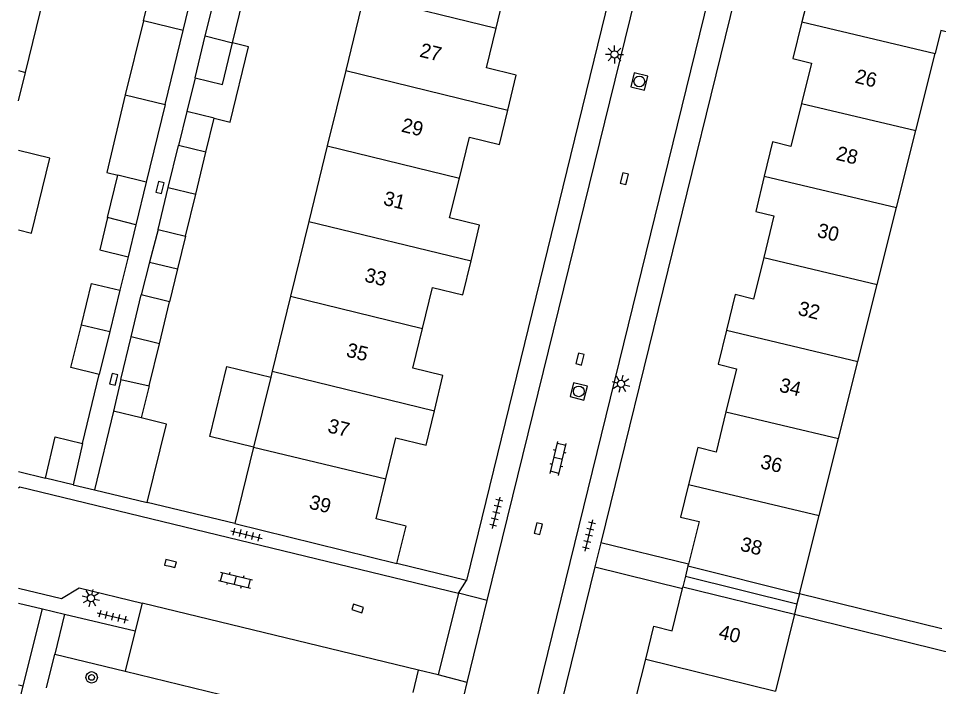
# Model space of a CAD drawing. Extents: x 128000 to 131008, y 398996 to 402500.
# Drawn here: x 128000 to 128064.3, y 399441.3 to 399488 of the extents above; entities that cross this region are included whole.
import ezdxf

# ---------------------------------------------------------------- set-up
doc = ezdxf.new("R2010")
doc.units = 0
for name, color, linetype in [('gg-afsc-erfafscheiding', 7, 'Continuous'), ('gg-afsc-hekwerk', 7, 'Continuous'), ('gg-afsc-muur', 7, 'Continuous'), ('gg-anno-huisnummerreeks BGT', 7, 'Continuous'), ('gg-bbg-bijgebouw', 7, 'Continuous'), ('gg-bbg-gedigitaliseerde bebouwing', 7, 'Continuous'), ('gg-bbg-gedigitaliseerde bijgebouw', 7, 'Continuous'), ('gg-bbg-hoofdgebouw', 7, 'Continuous'), ('gg-bbg-luifel en loopbrug', 7, 'Continuous'), ('gg-bbg-onder overbouw', 7, 'Continuous'), ('gg-bbg-pand overbouw', 7, 'Continuous'), ('gg-bbg-tussenscheiding', 7, 'Continuous'), ('gg-bbg-tussenscheiding niveau 01', 7, 'Continuous'), ('gg-knt-verharding', 7, 'Continuous'), ('gg-knt-verharding nz', 7, 'Continuous'), ('gt-grn-weggrens', 7, 'Continuous'), ('gt-symb-boom', 7, 'Continuous'), ('gt-symb-klinker verharding', 7, 'Continuous'), ('gt-symb-kolk', 7, 'Continuous'), ('gt-symb-lichtmast', 7, 'Continuous'), ('gt-symb-rioolschacht', 7, 'Continuous'), ('gt-symb-tegel verharding', 7, 'Continuous')]:
    doc.layers.add(name, color=color, linetype=linetype)

# ---------------------------------------------------------------- blocks, each defined once
blk = doc.blocks.new('gt0-KOLK')
at = {"layer": 'gt-symb-kolk'}
blk.add_lwpolyline([(0, 0), (0.375, 0), (0.375, 0.4), (-0.375, 0.4), (-0.375, 0), (0, 0)], dxfattribs=at)
blk = doc.blocks.new('gt0-LMAST')
at = {"layer": 'gt-symb-lichtmast'}
for p, q in [((-0.182, 0.173), (-0.447, 0.438)), ((-0.005, 0.246), (-0.005, 0.621)), ((0.172, 0.173), (0.437, 0.438)), ((-0.255, -0.004), (-0.63, -0.004)), ((-0.182, -0.181), (-0.447, -0.446)), ((-0.005, -0.254), (-0.005, -0.629)), ((0.437, -0.446), (0.172, -0.181)), ((0.245, -0.004), (0.62, -0.004))]:
    blk.add_line(p, q, dxfattribs=at)
blk.add_circle((-0.005, -0.004), 0.25, dxfattribs=at)
blk = doc.blocks.new('gt0-RS')
at = {"layer": 'gt-symb-rioolschacht'}
blk.add_lwpolyline([(-0.5, -0.5), (0.5, -0.5), (0.5, 0.5), (-0.5, 0.5)], close=True, dxfattribs=at)
blk.add_circle((0, 0), 0.375, dxfattribs=at)
blk = doc.blocks.new('gt0-TEG1')
at = {"layer": 'gt-symb-tegel verharding'}
for p, q in [((-1.125, 0), (1.125, 0)), ((-0.9, -0.25), (-0.9, 0.25)), ((-0.45, -0.25), (-0.45, 0.25)), ((0, -0.25), (0, 0.25)), ((0.45, -0.25), (0.45, 0.25)), ((0.9, -0.25), (0.9, 0.25))]:
    blk.add_line(p, q, dxfattribs=at)
blk = doc.blocks.new('gt0-KL1')
at = {"layer": 'gt-symb-klinker verharding'}
for p, q in [((-1.15, 0.3), (1.15, 0.3)), ((-1, -0.3), (-1, 0.3)), ((-0.5, 0.3), (-0.5, 0.45)), ((0, -0.3), (0, 0.3)), ((0.5, 0.3), (0.5, 0.45)), ((1, -0.3), (1, 0.3)), ((-1.15, -0.3), (1.15, -0.3)), ((-0.5, -0.45), (-0.5, -0.3)), ((0.5, -0.45), (0.5, -0.3))]:
    blk.add_line(p, q, dxfattribs=at)
blk = doc.blocks.new('gt0-BOOM')
at = {"layer": 'gt-symb-boom'}
for radius in [0.4, 0.2]:
    blk.add_circle((0, 0), radius, dxfattribs=at)

msp = doc.modelspace()

# ---------------------------------------------------------------- linework, layer by layer
at = {"layer": 'gg-afsc-erfafscheiding'}
for p, q in [((128007.665, 399471.364), (128007.09, 399469.019)), ((128004.48, 399458.323), (128005.656, 399463.142)), ((128064.553, 399445.371), (128054.591, 399447.82))]:
    msp.add_line(p, q, dxfattribs=at)
msp.add_lwpolyline([(128054.25, 399446.39), (128067.198, 399443.207), (128066.58, 399440.802)], dxfattribs=at)
at = {"layer": 'gg-afsc-hekwerk'}
for p, q in [((128001.967, 399441.245), (128002.542, 399443.609)), ((128002.542, 399443.609), (128007.47, 399442.41)), ((128007.47, 399442.41), (128026.82, 399437.72))]:
    msp.add_line(p, q, dxfattribs=at)
at = {"layer": 'gg-afsc-muur'}
for p, q in [((128000, 399456.352), (128001.888, 399455.886)), ((128015.13, 399452.72), (128009.009, 399454.186)), ((128046.827, 399449.877), (128040.705, 399451.381)), ((128040.294, 399449.707), (128046.421, 399448.191))]:
    msp.add_line(p, q, dxfattribs=at)
at = {"layer": 'gg-bbg-bijgebouw'}
for p, q in [((128006.652, 399460.575), (128005.317, 399455.085)), ((128008.59, 399460.103), (128006.652, 399460.575)), ((128001.888, 399455.886), (128002.578, 399458.787)), ((128004.48, 399458.323), (128003.831, 399455.424)), ((128003.831, 399455.424), (128001.888, 399455.886)), ((128005.317, 399455.085), (128009.009, 399454.186)), ((128000, 399447.174), (128001.69, 399446.76))]:
    msp.add_line(p, q, dxfattribs=at)
msp.add_lwpolyline([(128009.009, 399454.186), (128010.345, 399459.676), (128008.59, 399460.103)], dxfattribs=at)
at = {"layer": 'gg-bbg-gedigitaliseerde bebouwing'}
msp.add_line((128054.25, 399446.39), (128052.93, 399441.02), dxfattribs=at)
msp.add_lwpolyline([(128072.212, 399489.204), (128071.304, 399485.502), (128064.48, 399487.175), (128064.084, 399485.56)], dxfattribs=at)
at = {"layer": 'gg-bbg-gedigitaliseerde bijgebouw'}
for p, q in [((128011.516, 399487.159), (128012.822, 399492.516)), ((128013.062, 399486.782), (128013.778, 399489.713)), ((128014.968, 399486.313), (128015.683, 399489.25)), ((128008.733, 399487.836), (128007.472, 399482.662)), ((128010.254, 399481.984), (128011.516, 399487.159)), ((128012.346, 399483.85), (128013.062, 399486.782)), ((128010.254, 399481.984), (128008.936, 399476.577)), ((128010.477, 399476.202), (128011.195, 399479.142)), ((128013.11, 399478.676), (128011.195, 399479.142)), ((128012.395, 399475.738), (128013.11, 399478.676)), ((128006.231, 399474.108), (128006.953, 399477.065)), ((128008.936, 399476.577), (128008.21, 399473.59)), ((128009.76, 399473.269), (128010.477, 399476.202)), ((128011.68, 399472.802), (128012.395, 399475.738)), ((128008.21, 399473.59), (128006.231, 399474.108)), ((128009.76, 399473.269), (128011.68, 399472.802)), ((128007.09, 399469.019), (128006.385, 399466.13)), ((128007.877, 399465.767), (128008.584, 399468.702)), ((128010.565, 399468.22), (128008.584, 399468.702)), ((128009.851, 399465.286), (128010.565, 399468.22)), ((128006.385, 399466.13), (128005.656, 399463.142)), ((128007.16, 399462.79), (128007.877, 399465.767)), ((128009.138, 399462.355), (128009.851, 399465.286)), ((128007.16, 399462.79), (128009.138, 399462.355)), ((128002.578, 399458.787), (128004.48, 399458.323)), ((128000.341, 399441.385), (128001.69, 399446.76)), ((128000, 399440.024), (128000.341, 399441.385))]:
    msp.add_line(p, q, dxfattribs=at)
for points in [[(128008.733, 399487.836), (128010.04, 399493.194), (128012.822, 399492.516)], [(128012.346, 399483.85), (128014.256, 399483.385), (128014.968, 399486.313)], [(128007.472, 399482.662), (128006.172, 399477.253), (128006.953, 399477.065)], [(128004.402, 399466.611), (128005.108, 399469.503), (128007.09, 399469.019)], [(128005.656, 399463.142), (128003.674, 399463.625), (128004.402, 399466.611)]]:
    msp.add_lwpolyline(points, dxfattribs=at)
at = {"layer": 'gg-bbg-hoofdgebouw'}
for p, q in [((128055.71, 399491.59), (128054.769, 399487.766)), ((128000.487, 399484.241), (128001.781, 399489.524)), ((128024.156, 399489.589), (128022.878, 399484.37)), ((128062.732, 399480.183), (128064.084, 399485.56)), ((128000, 399482.251), (128000.487, 399484.241)), ((128022.878, 399484.37), (128021.59, 399479.105)), ((128061.379, 399474.806), (128062.732, 399480.183)), ((128021.59, 399479.105), (128020.297, 399473.827)), ((128060.026, 399469.428), (128061.379, 399474.806)), ((128020.297, 399473.827), (128019.017, 399468.596)), ((128058.674, 399464.052), (128060.026, 399469.428)), ((128019.017, 399468.596), (128017.736, 399463.363)), ((128057.321, 399458.675), (128058.674, 399464.052)), ((128017.634, 399462.948), (128016.439, 399458.066)), ((128017.736, 399463.363), (128017.634, 399462.948)), ((128055.969, 399453.298), (128057.321, 399458.675)), ((128016.439, 399458.066), (128015.13, 399452.72)), ((128054.591, 399447.82), (128055.969, 399453.298)), ((128015.13, 399452.72), (128026.45, 399449.94)), ((128046.827, 399449.877), (128046.8, 399449.77)), ((128046.421, 399448.191), (128046.45, 399448.31))]:
    msp.add_line(p, q, dxfattribs=at)
for points in [[(128033.39, 399487.338), (128034.08, 399490.17), (128036.18, 399489.65), (128036.778, 399492.07)], [(128054.769, 399487.766), (128054.14, 399485.21), (128055.431, 399484.89), (128054.739, 399482.075)], [(128034.201, 399481.588), (128034.8, 399484.04), (128032.71, 399484.55), (128033.39, 399487.338)], [(128030.825, 399476.851), (128031.531, 399479.72), (128033.621, 399479.21), (128034.201, 399481.588)], [(128054.739, 399482.075), (128054, 399479.07), (128052.72, 399479.39), (128052.138, 399476.994)], [(128031.639, 399471.085), (128032.24, 399473.56), (128030.14, 399474.07), (128030.825, 399476.851)], [(128052.138, 399476.994), (128051.54, 399474.53), (128052.81, 399474.22), (128052.094, 399471.306)], [(128052.094, 399471.306), (128051.38, 399468.4), (128050.1, 399468.72), (128049.491, 399466.226)], [(128028.251, 399466.355), (128028.95, 399469.21), (128031.06, 399468.7), (128031.639, 399471.085)], [(128029.073, 399460.599), (128029.67, 399463.06), (128027.57, 399463.57), (128028.251, 399466.355)], [(128049.491, 399466.226), (128048.91, 399463.85), (128050.19, 399463.54), (128049.452, 399460.538)], [(128025.683, 399455.853), (128026.38, 399458.71), (128028.49, 399458.2), (128029.073, 399460.599)], [(128049.452, 399460.538), (128048.76, 399457.72), (128047.48, 399458.03), (128046.841, 399455.459)], [(128026.45, 399449.94), (128027.11, 399452.54), (128025.001, 399453.06), (128025.683, 399455.853)], [(128046.841, 399455.459), (128046.27, 399453.16), (128047.58, 399452.87), (128046.827, 399449.877)], [(128043.846, 399443.25), (128044.42, 399445.56), (128045.69, 399445.22), (128046.421, 399448.191)], [(128043.816, 399437.551), (128044.51, 399440.37), (128043.21, 399440.69), (128043.846, 399443.25)]]:
    msp.add_lwpolyline(points, dxfattribs=at)
at = {"layer": 'gg-bbg-luifel en loopbrug'}
for p, q in [((128012.346, 399483.85), (128011.771, 399481.496)), ((128011.771, 399481.496), (128011.195, 399479.142)), ((128013.683, 399481.031), (128011.771, 399481.496)), ((128013.11, 399478.676), (128013.683, 399481.031)), ((128008.21, 399473.59), (128007.665, 399471.364)), ((128009.76, 399473.269), (128009.172, 399470.986)), ((128011.68, 399472.802), (128011.123, 399470.511)), ((128009.172, 399470.986), (128008.584, 399468.702)), ((128009.172, 399470.986), (128011.123, 399470.511)), ((128011.123, 399470.511), (128010.565, 399468.22)), ((128007.16, 399462.79), (128006.652, 399460.575)), ((128009.138, 399462.355), (128008.59, 399460.103))]:
    msp.add_line(p, q, dxfattribs=at)
for points in [[(128013.683, 399481.031), (128014.803, 399480.758), (128016.083, 399486.023), (128014.968, 399486.313)], [(128000, 399473.229), (128000.927, 399473.003), (128002.202, 399478.244), (128000, 399478.78)], [(128006.231, 399474.108), (128005.681, 399471.847), (128007.665, 399471.364)], [(128016.439, 399458.066), (128013.387, 399458.808), (128014.575, 399463.692), (128017.634, 399462.948)]]:
    msp.add_lwpolyline(points, dxfattribs=at)
at = {"layer": 'gg-bbg-onder overbouw'}
for p, q in [((128046.8, 399449.77), (128054.591, 399447.82)), ((128046.45, 399448.31), (128054.25, 399446.39))]:
    msp.add_line(p, q, dxfattribs=at)
at = {"layer": 'gg-bbg-pand overbouw'}
for p, q in [((128046.8, 399449.77), (128046.625, 399449.04)), ((128046.625, 399449.04), (128046.45, 399448.31)), ((128054.591, 399447.82), (128054.421, 399447.105)), ((128054.421, 399447.105), (128054.25, 399446.39))]:
    msp.add_line(p, q, dxfattribs=at)
at = {"layer": 'gg-bbg-tussenscheiding'}
for p, q in [((128024.156, 399489.589), (128033.39, 399487.338)), ((128011.516, 399487.159), (128008.733, 399487.836)), ((128054.769, 399487.766), (128064.084, 399485.56)), ((128013.062, 399486.782), (128014.968, 399486.313)), ((128000, 399484.359), (128000.487, 399484.241)), ((128022.878, 399484.37), (128034.201, 399481.588)), ((128007.472, 399482.662), (128010.254, 399481.984)), ((128054.739, 399482.075), (128062.732, 399480.183)), ((128021.59, 399479.105), (128030.825, 399476.851)), ((128008.936, 399476.577), (128006.953, 399477.065)), ((128052.138, 399476.994), (128061.379, 399474.806)), ((128010.477, 399476.202), (128012.395, 399475.738)), ((128020.297, 399473.827), (128031.639, 399471.085)), ((128052.094, 399471.306), (128060.026, 399469.428)), ((128019.017, 399468.596), (128028.251, 399466.355)), ((128004.402, 399466.611), (128006.385, 399466.13)), ((128049.491, 399466.226), (128058.674, 399464.052)), ((128009.851, 399465.286), (128007.877, 399465.767)), ((128017.736, 399463.363), (128029.073, 399460.599)), ((128049.452, 399460.538), (128057.321, 399458.675)), ((128016.439, 399458.066), (128025.683, 399455.853)), ((128046.841, 399455.459), (128055.969, 399453.298)), ((128043.846, 399443.25), (128052.93, 399441.02)), ((128000, 399441.467), (128000.341, 399441.385))]:
    msp.add_line(p, q, dxfattribs=at)
at = {"layer": 'gg-bbg-tussenscheiding niveau 01'}
msp.add_line((128046.625, 399449.04), (128054.421, 399447.105), dxfattribs=at)
at = {"layer": 'gg-knt-verharding'}
for p, q in [((128042.989, 399496.39), (128031.33, 399448.74)), ((128051.27, 399494.35), (128040.705, 399451.381)), ((128032.775, 399447.345), (128044.065, 399493.284)), ((128048.865, 399492.067), (128035.151, 399436.183)), ((128031.33, 399448.74), (128026.45, 399449.94)), ((128030.77, 399447.85), (128029.33, 399442.15)), ((128008.655, 399447.162), (128008.15, 399445.23)), ((128031.37, 399441.625), (128032.775, 399447.345)), ((128001.69, 399446.76), (128003.221, 399446.397)), ((128003.221, 399446.397), (128002.542, 399443.609)), ((128003.221, 399446.397), (128008.15, 399445.23)), ((128008.15, 399445.23), (128007.47, 399442.41)), ((128027.604, 399440.918), (128027.969, 399442.48)), ((128029.33, 399442.15), (128027.969, 399442.48)), ((128030.331, 399437.399), (128031.37, 399441.625))]:
    msp.add_line(p, q, dxfattribs=at)
for points in [[(128000, 399455.225), (128000.11, 399455.3), (128030.77, 399447.85)], [(128040.294, 399449.707), (128028.995, 399403.745), (128032.814, 399402.791)], [(128000, 399448.22), (128003.01, 399447.48), (128004.25, 399448.23), (128008.655, 399447.162)]]:
    msp.add_lwpolyline(points, dxfattribs=at)
at = {"layer": 'gg-knt-verharding nz'}
msp.add_line((128027.969, 399442.48), (128008.655, 399447.162), dxfattribs=at)
at = {"layer": 'gt-grn-weggrens'}
for p, q in [((128003.831, 399455.424), (128005.317, 399455.085)), ((128040.705, 399451.381), (128040.294, 399449.707)), ((128030.77, 399447.85), (128031.33, 399448.74)), ((128032.775, 399447.345), (128030.77, 399447.85)), ((128031.37, 399441.625), (128029.33, 399442.15))]:
    msp.add_line(p, q, dxfattribs=at)

# ---------------------------------------------------------------- block references
at = {"layer": 'gt-symb-boom'}
msp.add_blockref('gt0-BOOM', (128005.118, 399441.979), dxfattribs=at)
at = {"layer": 'gt-symb-klinker verharding'}
for p, rotation in [((128037.729, 399457.271), 76.17220496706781), ((128015.179, 399448.775), -13.64723833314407)]:
    msp.add_blockref('gt0-KL1', p, dxfattribs=dict(at, rotation=rotation))
at = {"layer": 'gt-symb-kolk'}
for p, rotation in [((128042.545, 399476.76), 76.22785456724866), ((128010.094, 399476.149), 76.3527616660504), ((128039.451, 399464.16), 75.28268885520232), ((128006.852, 399462.746), 76.35276166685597), ((128036.531, 399452.322), 75.5189656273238), ((128010.58, 399449.739), -13.772145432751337), ((128023.654, 399446.6), -17.40188791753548)]:
    msp.add_blockref('gt0-KOLK', p, dxfattribs=dict(at, rotation=rotation))
at = {"layer": 'gt-symb-lichtmast'}
for p, rotation in [((128041.661, 399485.495), 90), ((128042.119, 399462.485), 76.17220496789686), ((128005.068, 399447.517), 76.35276166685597)]:
    msp.add_blockref('gt0-LMAST', p, dxfattribs=dict(at, rotation=rotation))
at = {"layer": 'gt-symb-rioolschacht', "rotation": 76.17220496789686}
for p in [(128043.401, 399483.606), (128039.167, 399461.957)]:
    msp.add_blockref('gt0-RS', p, dxfattribs=at)
at = {"layer": 'gt-symb-tegel verharding'}
for p, rotation in [((128033.398, 399453.481), 76.17220496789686), ((128039.876, 399451.893), 76.17220496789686), ((128015.939, 399451.955), -13.64723833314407), ((128006.59, 399446.23), -13.64723833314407)]:
    msp.add_blockref('gt0-TEG1', p, dxfattribs=dict(at, rotation=rotation))

# ---------------------------------------------------------------- texts
at = {"layer": 'gg-anno-huisnummerreeks BGT'}
for s, rotation, p in [('27', 346.3, (128027.987, 399485.344)), ('26', 346.2, (128058.414, 399483.528)), ('29', 346.2, (128026.707, 399480.111)), ('28', 346.2, (128057.091, 399478.145)), ('31', 346.2, (128025.449, 399475.001)), ('30', 346.2, (128055.769, 399472.76)), ('33', 346.2, (128024.137, 399469.641)), ('32', 346.2, (128054.431, 399467.312)), ('35', 346.2, (128022.855, 399464.402)), ('34', 346.2, (128053.119, 399461.956)), ('37', 346.3, (128021.56, 399459.108)), ('36', 346.2, (128051.806, 399456.608)), ('39', 346.3, (128020.259, 399453.782)), ('38', 345.9, (128050.395, 399450.849)), ('40', 346.2, (128048.883, 399444.712))]:
    msp.add_text(s, height=1, rotation=rotation, dxfattribs=at).set_placement(p)

doc.saveas('drawing.dxf')
